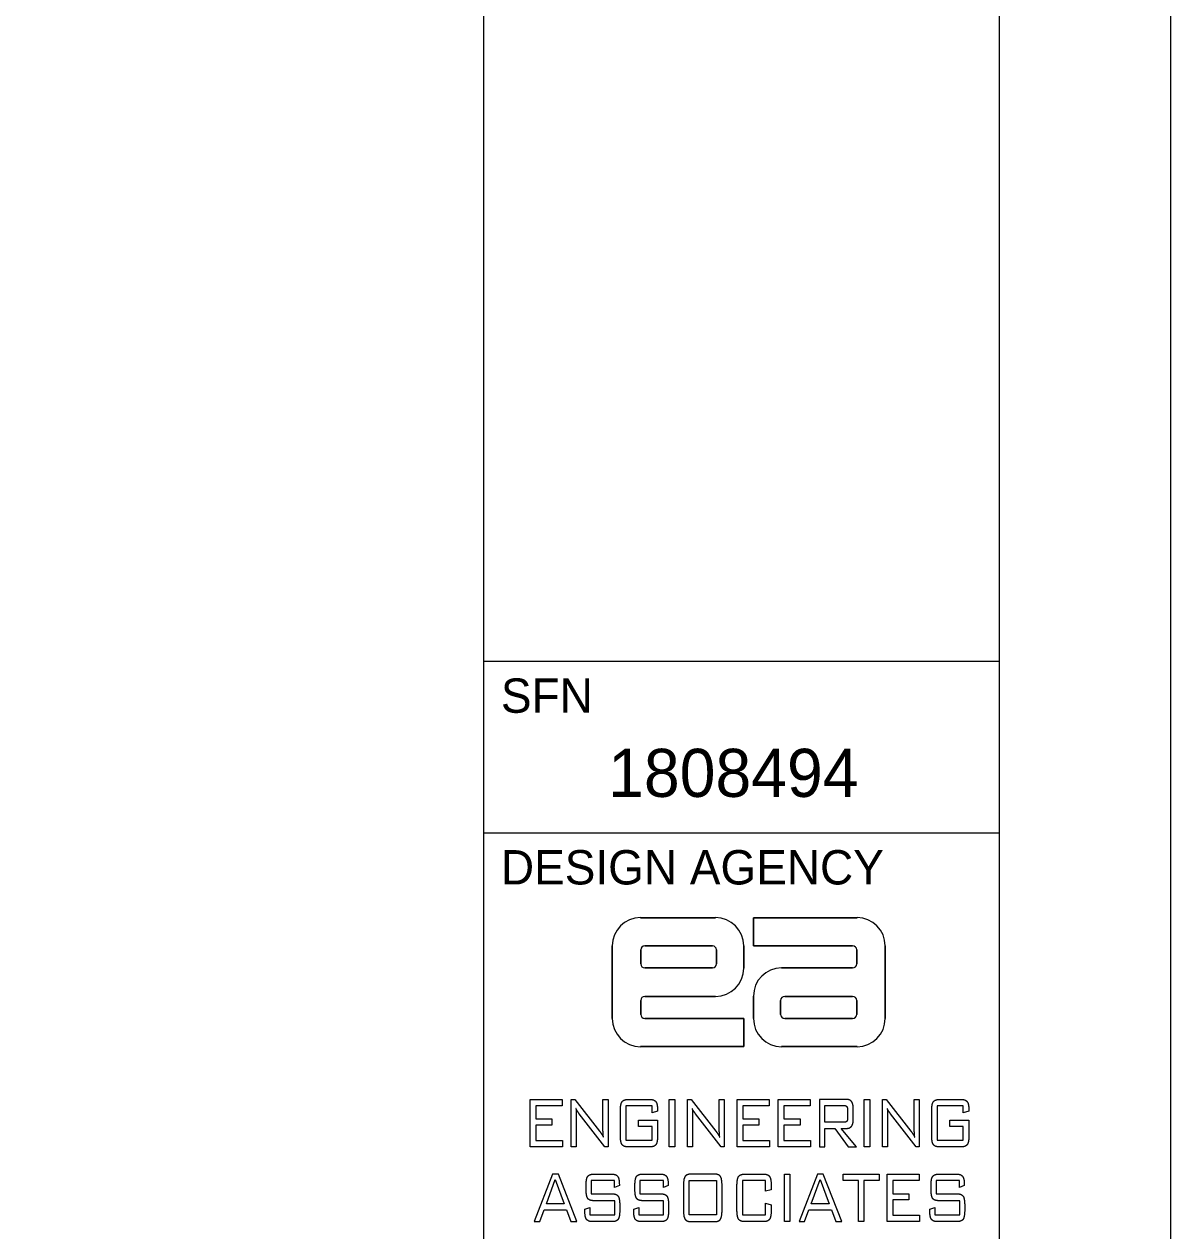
# Model space of a CAD drawing. Extents: x 0 to 34, y 0 to 22.
# Drawn here: x 30.662 to 34, y 3.841 to 7.356 of the extents above; entities that cross this region are included whole.
import ezdxf

# ---------------------------------------------------------------- set-up
doc = ezdxf.new("R2010")
doc.units = 0
for name, color, linetype in [('SH_Border', 7, 'Continuous'), ('SH_Cut_Line', 7, 'Continuous'), ('SH_Data', 7, 'Continuous'), ('TX_X_20', 7, 'Continuous')]:
    doc.layers.add(name, color=color, linetype=linetype)

msp = doc.modelspace()

# ---------------------------------------------------------------- linework, layer by layer
at = {"layer": 'SH_Border'}
for p, q in [((32, 0.5), (32, 21.5)), ((32, 5.5), (33.5, 5.5)), ((32, 5), (33.5, 5))]:
    msp.add_line(p, q, dxfattribs=at)
msp.add_lwpolyline([(1.5, 21.5), (33.5, 21.5), (33.5, 0.5), (1.5, 0.5)], close=True, dxfattribs=at)
at = {"layer": 'SH_Cut_Line'}
msp.add_lwpolyline([(0, 0), (34, 0), (34, 22), (0, 22)], close=True, dxfattribs=at)
at = {"layer": 'SH_Data'}
msp.add_line((32.75, 4), (32.75, 4), dxfattribs=at)
at = {"layer": 'TX_X_20'}
for p, q in [((32.6745, 4.7533), (32.456, 4.7533)), ((32.456, 4.7533), (32.6745, 4.7533)), ((32.785, 4.7533), (33.0865, 4.7533)), ((32.785, 4.6713), (32.785, 4.7533)), ((32.3739, 4.6713), (32.3739, 4.4597)), ((32.3739, 4.4597), (32.3739, 4.6713)), ((32.457, 4.6189), (32.457, 4.6594)), ((32.457, 4.6594), (32.457, 4.6189)), ((32.4688, 4.6713), (32.6656, 4.6713)), ((32.6656, 4.6713), (32.4688, 4.6713)), ((32.6775, 4.6594), (32.6775, 4.6189)), ((32.6775, 4.6189), (32.6775, 4.6594)), ((32.7566, 4.606), (32.7566, 4.6713)), ((32.7566, 4.6713), (32.7566, 4.606)), ((33.0737, 4.6713), (32.785, 4.6713)), ((33.0855, 4.6594), (33.0855, 4.6189)), ((33.0855, 4.6189), (33.0855, 4.6594)), ((33.1686, 4.4597), (33.1686, 4.6713)), ((33.1686, 4.6713), (33.1686, 4.4597)), ((32.6656, 4.607), (32.4688, 4.607)), ((32.4688, 4.607), (32.6656, 4.607)), ((33.0737, 4.607), (32.8671, 4.607)), ((32.8671, 4.607), (33.0737, 4.607)), ((32.457, 4.4716), (32.457, 4.5121)), ((32.457, 4.5121), (32.457, 4.4716)), ((32.4688, 4.524), (32.6745, 4.524)), ((32.6745, 4.524), (32.4688, 4.524)), ((32.785, 4.525), (32.785, 4.4597)), ((32.785, 4.4597), (32.785, 4.525)), ((32.8641, 4.4716), (32.8641, 4.5121)), ((32.8641, 4.5121), (32.8641, 4.4716)), ((32.876, 4.524), (33.0737, 4.524)), ((33.0737, 4.524), (32.876, 4.524)), ((33.0855, 4.5121), (33.0855, 4.4716)), ((33.0855, 4.4716), (33.0855, 4.5121)), ((32.4688, 4.4597), (32.7566, 4.4597)), ((32.7566, 4.4597), (32.7566, 4.3777)), ((33.0737, 4.4597), (32.876, 4.4597)), ((32.876, 4.4597), (33.0737, 4.4597)), ((32.7566, 4.3777), (32.456, 4.3777)), ((32.8671, 4.3777), (33.0865, 4.3777)), ((33.0865, 4.3777), (32.8671, 4.3777)), ((32.4205, 4.224), (32.4832, 4.224)), ((33.3267, 4.224), (33.3893, 4.224)), ((32.3978, 4.1184), (32.3978, 4.1913)), ((33.0591, 4.1918), (33.0591, 4.1716)), ((33.0755, 4.1662), (33.0755, 4.1972)), ((33.3039, 4.1184), (33.3039, 4.1913)), ((32.4832, 4.0856), (32.4205, 4.0856)), ((33.3893, 4.0856), (33.3267, 4.0856)), ((32.3205, 4.0065), (32.3719, 4.0065)), ((32.4627, 4.0065), (32.5142, 4.0065)), ((32.6711, 4.0065), (32.6041, 4.0065)), ((32.7599, 4.0065), (32.814, 4.0065)), ((33.3246, 4.0065), (33.3761, 4.0065)), ((32.2979, 3.9618), (32.2979, 3.9738)), ((32.4401, 3.9618), (32.4401, 3.9738)), ((32.5814, 3.9738), (32.5814, 3.9009)), ((32.6936, 3.9009), (32.6936, 3.9738)), ((32.7371, 3.9009), (32.7371, 3.9738)), ((33.302, 3.9618), (33.302, 3.9738)), ((32.3958, 3.9164), (32.3958, 3.9009)), ((32.538, 3.9164), (32.538, 3.9009)), ((33.3999, 3.9164), (33.3999, 3.9009)), ((32.3733, 3.8681), (32.3169, 3.8681)), ((32.5155, 3.8681), (32.4591, 3.8681)), ((32.6041, 3.8681), (32.6711, 3.8681)), ((32.814, 3.8681), (32.7599, 3.8681)), ((33.3774, 3.8681), (33.321, 3.8681))]:
    msp.add_line(p, q, dxfattribs=at)
for points in [[(33.0865, 4.7533), (32.785, 4.7533), (32.785, 4.6713), (33.0737, 4.6713)], [(32.456, 4.3777), (32.7566, 4.3777), (32.7566, 4.4597), (32.4688, 4.4597)], [(32.2695, 4.1672), (32.2695, 4.0856), (32.2547, 4.0856), (32.2547, 4.224), (32.2649, 4.224), (32.3374, 4.1315)], [(32.3469, 4.1481), (32.3469, 4.224), (32.3617, 4.224), (32.3617, 4.0856), (32.3526, 4.0856), (32.2782, 4.1819)], [(32.608, 4.1672), (32.608, 4.0856), (32.5932, 4.0856), (32.5932, 4.224), (32.6034, 4.224), (32.6759, 4.1315)], [(32.6854, 4.1481), (32.6854, 4.224), (32.7002, 4.224), (32.7002, 4.0856), (32.6912, 4.0856), (32.6168, 4.1819)], [(33.055, 4.224), (32.9769, 4.224), (32.9769, 4.0856), (32.9932, 4.0856), (32.9932, 4.1395), (33.0217, 4.1395), (33.0611, 4.0856), (33.0851, 4.0856), (33.0408, 4.1395), (33.055, 4.1395)], [(33.1756, 4.1672), (33.1756, 4.0856), (33.1608, 4.0856), (33.1608, 4.224), (33.171, 4.224), (33.2435, 4.1315)], [(33.253, 4.1481), (33.253, 4.224), (33.2678, 4.224), (33.2678, 4.0856), (33.2588, 4.0856), (33.1844, 4.1819)], [(32.5059, 4.1929), (32.5059, 4.1895), (32.4898, 4.1849), (32.4898, 4.2052), (32.4139, 4.2052), (32.4139, 4.1049), (32.4898, 4.1049), (32.4898, 4.1456), (32.4506, 4.1456), (32.4506, 4.1632), (32.5059, 4.1632), (32.5059, 4.1184)], [(33.0487, 4.1574), (32.9932, 4.1574), (32.9932, 4.2062), (33.0487, 4.2062)], [(33.4121, 4.1929), (33.4121, 4.1895), (33.3959, 4.1849), (33.3959, 4.2052), (33.3201, 4.2052), (33.3201, 4.1049), (33.3959, 4.1049), (33.3959, 4.1456), (33.3567, 4.1456), (33.3567, 4.1632), (33.4121, 4.1632), (33.4121, 4.1184)], [(32.3947, 3.9762), (32.3947, 3.9733), (32.3808, 3.9676), (32.3808, 3.9877), (32.3124, 3.9877), (32.3124, 3.9491), (32.3733, 3.9491)], [(32.5369, 3.9762), (32.5369, 3.9733), (32.523, 3.9676), (32.523, 3.9877), (32.4546, 3.9877), (32.4546, 3.9491), (32.5155, 3.9491)], [(32.8366, 3.9738), (32.8366, 3.9608), (32.8204, 3.9565), (32.8204, 3.9877), (32.7533, 3.9877), (32.7533, 3.8874), (32.8204, 3.8874), (32.8204, 3.9221), (32.8366, 3.9172), (32.8366, 3.9009)], [(33.3988, 3.9762), (33.3988, 3.9733), (33.3849, 3.9676), (33.3849, 3.9877), (33.3165, 3.9877), (33.3165, 3.9491), (33.3774, 3.9491)], [(32.2942, 3.9009), (32.2942, 3.9047), (32.3092, 3.9096), (32.3092, 3.8874), (32.3813, 3.8874), (32.3813, 3.929), (32.3205, 3.929)], [(32.4364, 3.9009), (32.4364, 3.9047), (32.4514, 3.9096), (32.4514, 3.8874), (32.5235, 3.8874), (32.5235, 3.929), (32.4627, 3.929)], [(33.2983, 3.9009), (33.2983, 3.9047), (33.3133, 3.9096), (33.3133, 3.8874), (33.3854, 3.8874), (33.3854, 3.929), (33.3246, 3.929)]]:
    msp.add_lwpolyline(points, dxfattribs=at)
for points in [[(32.1351, 4.0856), (32.1351, 4.224), (32.2283, 4.224), (32.2283, 4.2055), (32.1513, 4.2055), (32.1513, 4.167), (32.1984, 4.167), (32.1984, 4.1487), (32.1513, 4.1487), (32.1513, 4.1046), (32.2291, 4.1046), (32.2291, 4.0856)], [(32.5396, 4.0856), (32.5396, 4.224), (32.5558, 4.224), (32.5558, 4.0856)], [(32.7376, 4.0856), (32.7376, 4.224), (32.8309, 4.224), (32.8309, 4.2055), (32.7539, 4.2055), (32.7539, 4.167), (32.801, 4.167), (32.801, 4.1487), (32.7539, 4.1487), (32.7539, 4.1046), (32.8316, 4.1046), (32.8316, 4.0856)], [(32.8573, 4.0856), (32.8573, 4.224), (32.9505, 4.224), (32.9505, 4.2055), (32.8735, 4.2055), (32.8735, 4.167), (32.9206, 4.167), (32.9206, 4.1487), (32.8735, 4.1487), (32.8735, 4.1046), (32.9513, 4.1046), (32.9513, 4.0856)], [(33.1072, 4.0856), (33.1072, 4.224), (33.1234, 4.224), (33.1234, 4.0856)], [(32.1472, 3.8681), (32.1631, 3.8681), (32.1755, 3.9023), (32.241, 3.9023), (32.2534, 3.8681), (32.2712, 3.8681), (32.2174, 4.0065), (32.2001, 4.0065)], [(32.875, 3.8681), (32.875, 4.0065), (32.8912, 4.0065), (32.8912, 3.8681)], [(32.9182, 3.8681), (32.9341, 3.8681), (32.9465, 3.9023), (33.012, 3.9023), (33.0244, 3.8681), (33.0422, 3.8681), (32.9884, 4.0065), (32.9711, 4.0065)], [(33.1068, 3.9877), (33.1068, 3.8681), (33.0907, 3.8681), (33.0907, 3.9877), (33.0464, 3.9877), (33.0464, 4.0065), (33.1513, 4.0065), (33.1513, 3.9877)], [(33.1742, 3.8681), (33.1742, 4.0065), (33.2675, 4.0065), (33.2675, 3.988), (33.1905, 3.988), (33.1905, 3.9495), (33.2376, 3.9495), (33.2376, 3.9312), (33.1905, 3.9312), (33.1905, 3.8871), (33.2682, 3.8871), (33.2682, 3.8681)], [(32.1823, 3.9199), (32.2083, 3.9907), (32.2344, 3.9199)], [(32.5975, 3.8874), (32.5975, 3.9877), (32.6777, 3.9877), (32.6777, 3.8874)], [(32.9533, 3.9199), (32.9793, 3.9907), (33.0054, 3.9199)]]:
    msp.add_lwpolyline(points, close=True, dxfattribs=at)
for centre, radius, start, end in [((32.456, 4.6713), 0.0821, 90, 180), ((32.456, 4.6713), 0.0821, 90, 180), ((32.6745, 4.6713), 0.0821, 0, 90), ((32.6745, 4.6713), 0.0821, 0, 90), ((33.0865, 4.6713), 0.0821, 0, 90), ((33.0865, 4.6713), 0.0821, 0, 90), ((32.4688, 4.6594), 0.0119, 90, 180), ((32.4688, 4.6594), 0.0119, 90, 180), ((32.6656, 4.6594), 0.0119, 0, 90), ((32.6656, 4.6594), 0.0119, 0, 90), ((33.0737, 4.6594), 0.0119, 0, 90), ((33.0737, 4.6594), 0.0119, 0, 90), ((32.4688, 4.6189), 0.0119, 180, 270), ((32.4688, 4.6189), 0.0119, 180, 270), ((32.6656, 4.6189), 0.0119, 270, 0), ((32.6656, 4.6189), 0.0119, 270, 0), ((32.6745, 4.606), 0.0821, 270, 360), ((32.6745, 4.606), 0.0821, 270, 360), ((32.8671, 4.525), 0.0821, 90, 180), ((32.8671, 4.525), 0.0821, 90, 180), ((33.0737, 4.6189), 0.0119, 270, 0), ((33.0737, 4.6189), 0.0119, 270, 0), ((32.4688, 4.5121), 0.0119, 90, 180), ((32.4688, 4.5121), 0.0119, 90, 180), ((32.876, 4.5121), 0.0119, 90, 180), ((32.876, 4.5121), 0.0119, 90, 180), ((33.0737, 4.5121), 0.0119, 0, 90), ((33.0737, 4.5121), 0.0119, 0, 90), ((32.4688, 4.4716), 0.0119, 180, 270), ((32.4688, 4.4716), 0.0119, 180, 270), ((32.876, 4.4716), 0.0119, 180, 270), ((32.876, 4.4716), 0.0119, 180, 270), ((33.0737, 4.4716), 0.0119, 270, 0), ((33.0737, 4.4716), 0.0119, 270, 0), ((32.456, 4.4597), 0.0821, 180, 270), ((32.456, 4.4597), 0.0821, 180, 270), ((32.8671, 4.4597), 0.0821, 180, 270), ((32.8671, 4.4597), 0.0821, 180, 270), ((33.0865, 4.4597), 0.0821, 270, 360), ((33.0865, 4.4597), 0.0821, 270, 360)]:
    msp.add_arc(centre, radius, start, end, dxfattribs=at)
for points in [[(32.4025, 4.2171), (32.4072, 4.224), (32.4205, 4.224)], [(32.4832, 4.224), (32.4962, 4.224), (32.5011, 4.2173)], [(32.5011, 4.2173), (32.5059, 4.2105), (32.5059, 4.1929)], [(33.0707, 4.2177), (33.0659, 4.224), (33.055, 4.224)], [(33.0755, 4.1972), (33.0755, 4.2113), (33.0707, 4.2177)], [(33.3086, 4.2171), (33.3134, 4.224), (33.3267, 4.224)], [(33.3893, 4.224), (33.4023, 4.224), (33.4072, 4.2173)], [(33.4072, 4.2173), (33.4121, 4.2105), (33.4121, 4.1929)], [(32.2766, 4.184), (32.2711, 4.191), (32.2684, 4.1975)], [(32.2684, 4.1975), (32.269, 4.1912), (32.2692, 4.184)], [(32.2692, 4.184), (32.2695, 4.1769), (32.2695, 4.1672)], [(32.2782, 4.1819), (32.2777, 4.1825), (32.2766, 4.184)], [(32.3978, 4.1913), (32.3978, 4.2102), (32.4025, 4.2171)], [(32.6151, 4.184), (32.6096, 4.191), (32.6069, 4.1975)], [(32.6069, 4.1975), (32.6075, 4.1912), (32.6078, 4.184)], [(32.6078, 4.184), (32.608, 4.1769), (32.608, 4.1672)], [(32.6168, 4.1819), (32.6162, 4.1825), (32.6151, 4.184)], [(33.0487, 4.2062), (33.0546, 4.2062), (33.0569, 4.2029)], [(33.0569, 4.2029), (33.0591, 4.1997), (33.0591, 4.1918)], [(33.1827, 4.184), (33.1772, 4.191), (33.1746, 4.1975)], [(33.1746, 4.1975), (33.1751, 4.1912), (33.1754, 4.184)], [(33.1754, 4.184), (33.1756, 4.1769), (33.1756, 4.1672)], [(33.1844, 4.1819), (33.1838, 4.1825), (33.1827, 4.184)], [(33.3039, 4.1913), (33.3039, 4.2102), (33.3086, 4.2171)], [(32.3473, 4.128), (32.3469, 4.1353), (32.3469, 4.1481)], [(32.6858, 4.128), (32.6854, 4.1353), (32.6854, 4.1481)], [(33.0569, 4.1606), (33.0547, 4.1574), (33.0487, 4.1574)], [(33.0591, 4.1716), (33.0591, 4.1637), (33.0569, 4.1606)], [(33.0707, 4.1459), (33.0755, 4.1522), (33.0755, 4.1662)], [(33.2534, 4.128), (33.253, 4.1353), (33.253, 4.1481)], [(32.3374, 4.1315), (32.3398, 4.1283), (32.3426, 4.1239)], [(32.3426, 4.1239), (32.3454, 4.1194), (32.3484, 4.114)], [(32.3484, 4.114), (32.3476, 4.1207), (32.3473, 4.128)], [(32.4025, 4.0926), (32.3978, 4.0995), (32.3978, 4.1184)], [(32.5059, 4.1184), (32.5059, 4.0994), (32.5012, 4.0925)], [(32.6759, 4.1315), (32.6784, 4.1283), (32.6812, 4.1239)], [(32.6812, 4.1239), (32.684, 4.1194), (32.6869, 4.114)], [(32.6869, 4.114), (32.6862, 4.1207), (32.6858, 4.128)], [(33.055, 4.1395), (33.0659, 4.1395), (33.0707, 4.1459)], [(33.2435, 4.1315), (33.246, 4.1283), (33.2488, 4.1239)], [(33.2488, 4.1239), (33.2516, 4.1194), (33.2545, 4.114)], [(33.2545, 4.114), (33.2538, 4.1207), (33.2534, 4.128)], [(33.3086, 4.0926), (33.3039, 4.0995), (33.3039, 4.1184)], [(33.4121, 4.1184), (33.4121, 4.0994), (33.4073, 4.0925)], [(32.4205, 4.0856), (32.4072, 4.0856), (32.4025, 4.0926)], [(32.5012, 4.0925), (32.4964, 4.0856), (32.4832, 4.0856)], [(33.3267, 4.0856), (33.3134, 4.0856), (33.3086, 4.0926)], [(33.4073, 4.0925), (33.4025, 4.0856), (33.3893, 4.0856)], [(32.3026, 3.9997), (32.3072, 4.0065), (32.3205, 4.0065)], [(32.3719, 4.0065), (32.3849, 4.0065), (32.3898, 3.9998)], [(32.4448, 3.9997), (32.4495, 4.0065), (32.4627, 4.0065)], [(32.5142, 4.0065), (32.5271, 4.0065), (32.532, 3.9998)], [(32.6041, 4.0065), (32.5908, 4.0065), (32.5861, 3.9996)], [(32.6889, 3.9997), (32.6842, 4.0065), (32.6711, 4.0065)], [(32.7419, 3.9997), (32.7467, 4.0065), (32.7599, 4.0065)], [(32.814, 4.0065), (32.8272, 4.0065), (32.8319, 3.9997)], [(33.3067, 3.9997), (33.3114, 4.0065), (33.3246, 4.0065)], [(33.3761, 4.0065), (33.389, 4.0065), (33.3939, 3.9998)], [(32.2979, 3.9738), (32.2979, 3.9928), (32.3026, 3.9997)], [(32.3898, 3.9998), (32.3947, 3.9931), (32.3947, 3.9762)], [(32.4401, 3.9738), (32.4401, 3.9928), (32.4448, 3.9997)], [(32.532, 3.9998), (32.5369, 3.9931), (32.5369, 3.9762)], [(32.5861, 3.9996), (32.5814, 3.9927), (32.5814, 3.9738)], [(32.6936, 3.9738), (32.6936, 3.9928), (32.6889, 3.9997)], [(32.7371, 3.9738), (32.7371, 3.9928), (32.7419, 3.9997)], [(32.8319, 3.9997), (32.8366, 3.9929), (32.8366, 3.9738)], [(33.302, 3.9738), (33.302, 3.9928), (33.3067, 3.9997)], [(33.3939, 3.9998), (33.3988, 3.9931), (33.3988, 3.9762)], [(32.3026, 3.9359), (32.2979, 3.9428), (32.2979, 3.9618)], [(32.3733, 3.9491), (32.3863, 3.9491), (32.391, 3.9423)], [(32.391, 3.9423), (32.3958, 3.9355), (32.3958, 3.9164)], [(32.4448, 3.9359), (32.4401, 3.9428), (32.4401, 3.9618)], [(32.5155, 3.9491), (32.5285, 3.9491), (32.5333, 3.9423)], [(32.5333, 3.9423), (32.538, 3.9355), (32.538, 3.9164)], [(33.3067, 3.9359), (33.302, 3.9428), (33.302, 3.9618)], [(33.3774, 3.9491), (33.3904, 3.9491), (33.3952, 3.9423)], [(33.3952, 3.9423), (33.3999, 3.9355), (33.3999, 3.9164)], [(32.3205, 3.929), (32.3072, 3.929), (32.3026, 3.9359)], [(32.4627, 3.929), (32.4495, 3.929), (32.4448, 3.9359)], [(33.3246, 3.929), (33.3114, 3.929), (33.3067, 3.9359)], [(32.2989, 3.875), (32.2942, 3.8819), (32.2942, 3.9009)], [(32.3169, 3.8681), (32.3037, 3.8681), (32.2989, 3.875)], [(32.3911, 3.875), (32.3865, 3.8681), (32.3733, 3.8681)], [(32.3958, 3.9009), (32.3958, 3.8818), (32.3911, 3.875)], [(32.4411, 3.875), (32.4364, 3.8819), (32.4364, 3.9009)], [(32.4591, 3.8681), (32.4459, 3.8681), (32.4411, 3.875)], [(32.5333, 3.875), (32.5287, 3.8681), (32.5155, 3.8681)], [(32.538, 3.9009), (32.538, 3.8818), (32.5333, 3.875)], [(32.5814, 3.9009), (32.5814, 3.882), (32.5861, 3.8751)], [(32.5861, 3.8751), (32.5908, 3.8681), (32.6041, 3.8681)], [(32.6711, 3.8681), (32.6842, 3.8681), (32.6889, 3.875)], [(32.6889, 3.875), (32.6936, 3.8818), (32.6936, 3.9009)], [(32.7419, 3.875), (32.7371, 3.8819), (32.7371, 3.9009)], [(32.7599, 3.8681), (32.7467, 3.8681), (32.7419, 3.875)], [(32.8319, 3.875), (32.8272, 3.8681), (32.814, 3.8681)], [(32.8366, 3.9009), (32.8366, 3.8818), (32.8319, 3.875)], [(33.3031, 3.875), (33.2983, 3.8819), (33.2983, 3.9009)], [(33.321, 3.8681), (33.3078, 3.8681), (33.3031, 3.875)], [(33.3953, 3.875), (33.3906, 3.8681), (33.3774, 3.8681)], [(33.3999, 3.9009), (33.3999, 3.8818), (33.3953, 3.875)]]:
    msp.add_open_spline(points, degree=2, dxfattribs=at)

# ---------------------------------------------------------------- texts
at = {"layer": 'SH_Data'}
for s, height, p in [('SFN', 0.1, (32.05, 5.35)), ('1808494', 0.14, (32.3621, 5.105)), ('DESIGN AGENCY', 0.1, (32.05, 4.85))]:
    msp.add_text(s, height=height, dxfattribs=at).set_placement(p)

doc.saveas('drawing.dxf')
